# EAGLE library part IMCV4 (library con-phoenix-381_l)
Invertierter Mini-Combicon 3.81mm vertikal 4-polig IMCV 1,5/4-G-3,81 (ohne Gegenstecker)
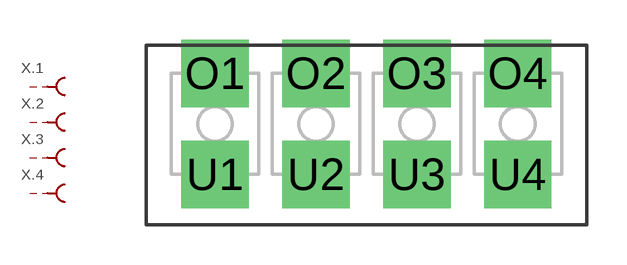
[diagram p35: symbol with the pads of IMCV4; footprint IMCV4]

Designator prefix X; gates .2=MCBU .1=MCBU .3=MCBU .4=MCBU

## IMCV4  [IMCV4]
O1  .1:S  pas
O2  .2:S  pas
O3  .3:S  pas
O4  .4:S  pas
U1  .1:SK  pas
U2  .2:SK  pas
U3  .3:SK  pas
U4  .4:SK  pas

## Footprint IMCV4 (pad centres in mm)
Mini-Combicon 3.81mm vertical 4-polig invertiert (ohne Gegenstecker)
drill 1.3 pad 2.54 square: O1 -5.715,1.905; O2 -1.905,1.905; O3 1.905,1.905; O4 5.715,1.905; U1 -5.715,-1.905; U2 -1.905,-1.905; U3 1.905,-1.905; U4 5.715,-1.905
